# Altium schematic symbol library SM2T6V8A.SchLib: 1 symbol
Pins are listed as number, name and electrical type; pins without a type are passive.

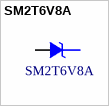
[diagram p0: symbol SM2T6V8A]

## SM2T6V8A
designator D?
footprint ST_DO-216AA
footprint PCBComponent_1
pins: 1 A, 2 K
